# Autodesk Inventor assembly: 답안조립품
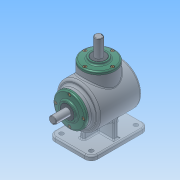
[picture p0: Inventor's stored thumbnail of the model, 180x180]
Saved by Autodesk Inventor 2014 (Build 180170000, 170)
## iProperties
Created: 2016-09
Part Number: 답안조립품
Document SubType Name: Assembly
Designer: net
Author: net
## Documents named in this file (14)
- C:\Users\net\Desktop\460907V1016\답안조립품.iam
- C:\Users\net\Desktop\460907V1016\답안본체.ipt
- C:\Users\net\Desktop\460907V1016\커버.ipt
- C:\Users\net\Desktop\460907V1016\오일실 17 32 8.ipt
- C:\Users\net\Desktop\460907V1016\M4.ipt
- C:\Users\net\Desktop\460907V1016\메인 축.ipt
- 메인 축.ipt
- C:\Users\net\Desktop\460907V1016\서브 축.ipt
- 서브 축.ipt
- C:\Users\net\Desktop\460907V1016\베어링 6203.ipt
- C:\Users\net\Desktop\460907V1016\키 5x5.ipt
- C:\Users\net\Desktop\460907V1016\키 4x4.ipt
- C:\Users\net\Desktop\460907V1016\서브 베벨기어.ipt
- C:\Users\net\Desktop\460907V1016\메인 베벨기어.ipt
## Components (8 placed, 1 different names)
1. M4:2
2. M4:3
3. M4:4
4. M4:5
5. M4:1
6. M4:6
7. M4:7
8. M4:8
